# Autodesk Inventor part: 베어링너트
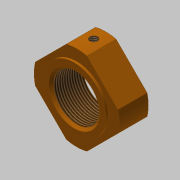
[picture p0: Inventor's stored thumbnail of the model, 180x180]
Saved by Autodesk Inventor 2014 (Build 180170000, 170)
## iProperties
Created: 2019-05
Part Number: 베어링너트
Material: 스테인리스강
Document SubType Name: Modeling
Designer: mduedu
Density: 1 g/cm^3
Appearance: Orange
Author: mduedu
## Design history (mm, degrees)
sketch "스케치1"
  geometry: C1 r 17.5 at (0, 0); 1 further point
  constraints: 1 centre point, 1 coincident
  dimensions: "d0" = 35 diameter of C1
extrude "돌출1" new body sketch "스케치1" distance "d1" = 12; taper "d2" = 0 deg
sketch "스케치2"
  geometry: L1 (-21.213, 0)-(0, 21.213); L2 (0, 21.213)-(21.213, 0); L3 (21.213, 0)-(0, -21.213); L4 (0, -21.213)-(-21.213, 0); L5 (-21.213, 0)-(21.213, 0); L6 (0, 21.213)-(0, -21.213); 1 further point
  constraints: 12 end point, 2 midpoint, 2 parallel, 1 perpendicular, 1 vertical
  dimensions: "d3" = 30 distance of L1.end L2.end; "d5" = 30 distance of L2.end L3.end
extrude "돌출2" sketch "스케치2" stored distance "d6" = 12; taper "d7" = 0 deg
sketch "스케치3"
  geometry: C1 r 13 at (0, 0); 1 further point
  constraints: 1 centre point, 1 coincident
  dimensions: "d8" = 26 diameter of C1
extrude "돌출3" join sketch "스케치3" distance "d9" = 1; taper "d10" = 0 deg
hole "구멍1" diameter "d13" = 18.917; stored, may be unused: countersink angle "d17" = 90 deg, drill point angle "d19" = 118 deg; dims "d11" = 10, "d12" = 10, "d14" = 6, "d15" = 4, "d16" = 2, "d18" = 8
chamfer "모따기1" distance "d20" = 1; stored, may be unused: second distance "d21" = 2, angle "d22" = 45 deg
node "작업 평면1"
sketch "스케치5"
  geometry: L1 (-4.233, 0)-(4.233, 0) reference; 3 further points
  constraints: 1 midpoint, 1 vertical alignment
  dimensions: "d31" = 5 distance from line of point (0, 5) L1
hole "구멍3" sketch "스케치5" at (0, 5) diameter "d32" = 3.242; stored, may be unused: countersink angle "d36" = 90 deg, drill point angle "d38" = 118 deg; dims "d33" = 6, "d34" = 4, "d35" = 2, "d37" = 8
node "솔리드1"
